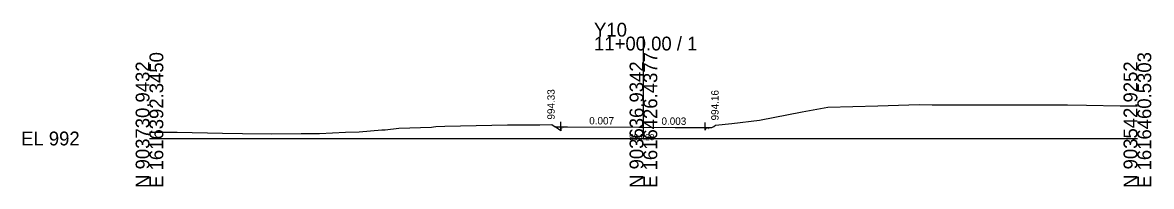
# Model space of a CAD drawing. Extents: x -26 to 203, y -10 to 3046.
# Drawn here: x -25.7 to 202.8, y 990.3 to 1023.5 of the extents above; entities that cross this region are included whole.
import ezdxf

# ---------------------------------------------------------------- set-up
doc = ezdxf.new("R2010")
doc.units = 0
for name, color, linetype in [('Exist Cross Section Cell', 7, 'Continuous'), ('Exist XS Center Line Elevation Label', 7, 'Continuous'), ('Exist XS Ground Line', 7, 'Continuous'), ('Prop XS Dump Level', 7, 'Continuous'), ('Prop XS Earthwork Shape', 7, 'Continuous'), ('Prop XS EOT Tick Mark', 7, 'Continuous'), ('Prop XS Finish Grade Pavement', 7, 'Continuous'), ('Prop XS Hydro Elevations', 7, 'Continuous'), ('Prop XS SE Text', 7, 'Continuous'), ('Prop XS Subgrade CurbGutter', 7, 'Continuous'), ('Prop XS Subgrade Earthwork', 7, 'Continuous')]:
    doc.layers.add(name, color=color, linetype=linetype)

msp = doc.modelspace()

# ---------------------------------------------------------------- linework, layer by layer
at = {"layer": 'Exist Cross Section Cell'}
for p, q in [((100, 1000), (100, 1020.61)), ((0, 1000), (100, 1000)), ((100, 1000), (200, 1000))]:
    msp.add_line(p, q, dxfattribs=at)
at = {"layer": 'Exist XS Ground Line'}
for p, q in [((132.14, 1005.4), (137.32, 1006.34)), ((137.32, 1006.34), (147.48, 1006.58)), ((147.48, 1006.58), (155.82, 1006.87)), ((155.82, 1006.87), (158.46, 1006.84)), ((158.46, 1006.84), (160.12, 1006.82)), ((160.12, 1006.82), (163.86, 1006.79)), ((163.86, 1006.79), (165.41, 1006.78)), ((165.41, 1006.78), (171.32, 1006.81)), ((171.32, 1006.81), (174.12, 1006.83)), ((174.12, 1006.83), (176.24, 1006.82)), ((176.24, 1006.82), (179.09, 1006.83)), ((179.09, 1006.83), (185.84, 1006.79)), ((185.84, 1006.79), (189.68, 1006.77)), ((189.68, 1006.77), (196.48, 1006.61)), ((196.48, 1006.61), (199.66, 1006.6)), ((199.66, 1006.6), (200, 1006.6)), ((117.88, 1003.01), (123.52, 1003.74)), ((123.52, 1003.74), (132.14, 1005.4)), ((0, 1001.27), (3.09, 1001.27)), ((3.09, 1001.27), (4.87, 1001.28)), ((4.87, 1001.28), (5.6, 1001.27)), ((5.6, 1001.27), (14.8, 1001.07)), ((14.8, 1001.07), (18.85, 1001.01)), ((18.85, 1001.01), (24.75, 1000.93)), ((24.75, 1000.93), (30.73, 1000.99)), ((30.73, 1000.99), (34.44, 1000.98)), ((34.44, 1000.98), (39.67, 1001.29)), ((39.67, 1001.29), (42.45, 1001.33)), ((42.45, 1001.33), (47.04, 1001.75)), ((47.04, 1001.75), (47.72, 1001.76)), ((47.72, 1001.76), (50.47, 1002.09)), ((50.47, 1002.09), (57.1, 1002.28)), ((57.1, 1002.28), (57.49, 1002.34)), ((57.49, 1002.34), (57.98, 1002.41)), ((57.98, 1002.41), (59.76, 1002.49)), ((59.76, 1002.49), (72.5, 1002.79)), ((72.5, 1002.79), (73.2, 1002.77)), ((73.2, 1002.77), (73.87, 1002.76)), ((73.87, 1002.76), (74.59, 1002.79)), ((74.59, 1002.79), (75.83, 1002.77)), ((75.83, 1002.77), (76.23, 1002.75)), ((76.23, 1002.75), (79.02, 1002.79)), ((79.02, 1002.79), (81.47, 1002.8)), ((81.47, 1002.8), (82.16, 1002.35)), ((82.16, 1002.35), (83.29, 1002.39)), ((83.29, 1002.39), (84.62, 1002.39)), ((84.62, 1002.39), (99.05, 1002.29)), ((99.05, 1002.29), (100, 1002.28)), ((100, 1002.28), (106.43, 1002.24)), ((106.43, 1002.24), (112.62, 1002.25)), ((112.62, 1002.25), (113.2, 1002.23)), ((113.2, 1002.23), (113.86, 1002.21)), ((113.86, 1002.21), (114.25, 1002.45)), ((114.25, 1002.45), (114.61, 1002.67)), ((114.61, 1002.67), (117.88, 1003.01))]:
    msp.add_line(p, q, dxfattribs=at)
at = {"layer": 'Prop XS Dump Level'}
for p, q in [((83.29, 1002.39), (100, 1002.28)), ((100, 1002.28), (112.47, 1002.25))]:
    msp.add_line(p, q, dxfattribs=at)
at = {"layer": 'Prop XS Earthwork Shape'}
for points in [[(83.29, 1001.56), (82.16, 1002.35), (83.29, 1002.39), (83.29, 1001.81)], [(112.47, 1001.66), (112.47, 1002.25), (112.62, 1002.25)]]:
    msp.add_lwpolyline(points, close=True, dxfattribs=at)
at = {"layer": 'Prop XS EOT Tick Mark'}
for p, q in [((83.29, 1002.39), (83.29, 1003.39)), ((112.47, 1002.25), (112.47, 1003.25))]:
    msp.add_line(p, q, dxfattribs=at)
at = {"layer": 'Prop XS Finish Grade Pavement'}
for p, q in [((83.29, 1002.39), (100, 1002.28)), ((100, 1002.28), (112.47, 1002.25))]:
    msp.add_line(p, q, dxfattribs=at)
at = {"layer": 'Prop XS Subgrade CurbGutter'}
for p, q in [((83.29, 1002.39), (83.29, 1001.81)), ((112.47, 1002.25), (112.47, 1001.67))]:
    msp.add_line(p, q, dxfattribs=at)
at = {"layer": 'Prop XS Subgrade Earthwork'}
for p, q in [((83.29, 1001.56), (82.16, 1002.35)), ((83.29, 1001.81), (83.29, 1002.39)), ((83.29, 1001.81), (83.29, 1001.56)), ((112.47, 1001.66), (112.47, 1002.25)), ((112.47, 1001.66), (112.62, 1002.25))]:
    msp.add_line(p, q, dxfattribs=at)

# ---------------------------------------------------------------- texts
at = {"layer": 'Exist Cross Section Cell'}
for s, p in [('Y10', (90, 1020.61)), ('11+00.00 / 1', (90, 1017.81)), ('EL 992', (-26, 998.6))]:
    msp.add_text(s, height=2.8, dxfattribs=at).set_placement(p)
for s, p in [('E 1616392.3450', (2.8, 990)), ('E 1616426.4377', (102.8, 990)), ('E 1616460.5303', (202.8, 990)), ('N 903730.9432', (0, 990)), ('N 903636.9342', (100, 990)), ('N 903542.9252', (200, 990))]:
    msp.add_text(s, height=2.8, rotation=90, dxfattribs=at).set_placement(p)
at = {"layer": 'Exist XS Center Line Elevation Label'}
msp.add_text('994.28', height=1.25, dxfattribs=at).set_placement((97.1, 999.66))
at = {"layer": 'Prop XS Dump Level'}
for p in [(83.29, 1002.09), (112.62, 1001.95)]:
    msp.add_text('Eop', height=0.3, dxfattribs=at).set_placement(p)
at = {"layer": 'Prop XS Hydro Elevations'}
for s, p in [('994.33', (82.04, 1003.83)), ('994.16', (115.22, 1003.66))]:
    msp.add_text(s, height=1.5, rotation=90, dxfattribs=at).set_placement(p)
at = {"layer": 'Prop XS SE Text'}
for s, rotation, p in [('0.007', 359.6224, (89.02, 1002.86)), ('0.003', 359.8338, (103.65, 1002.77))]:
    msp.add_text(s, height=1.5, rotation=rotation, dxfattribs=at).set_placement(p)

doc.saveas('drawing.dxf')
